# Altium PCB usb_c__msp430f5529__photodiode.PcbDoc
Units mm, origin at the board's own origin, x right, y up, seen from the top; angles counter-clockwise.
Board outline 62 x 34 mm, 2 copper layers (Top, Bottom), stack 0 mm thick; 27 components, 20 nets, 168 pads, 59 vias.
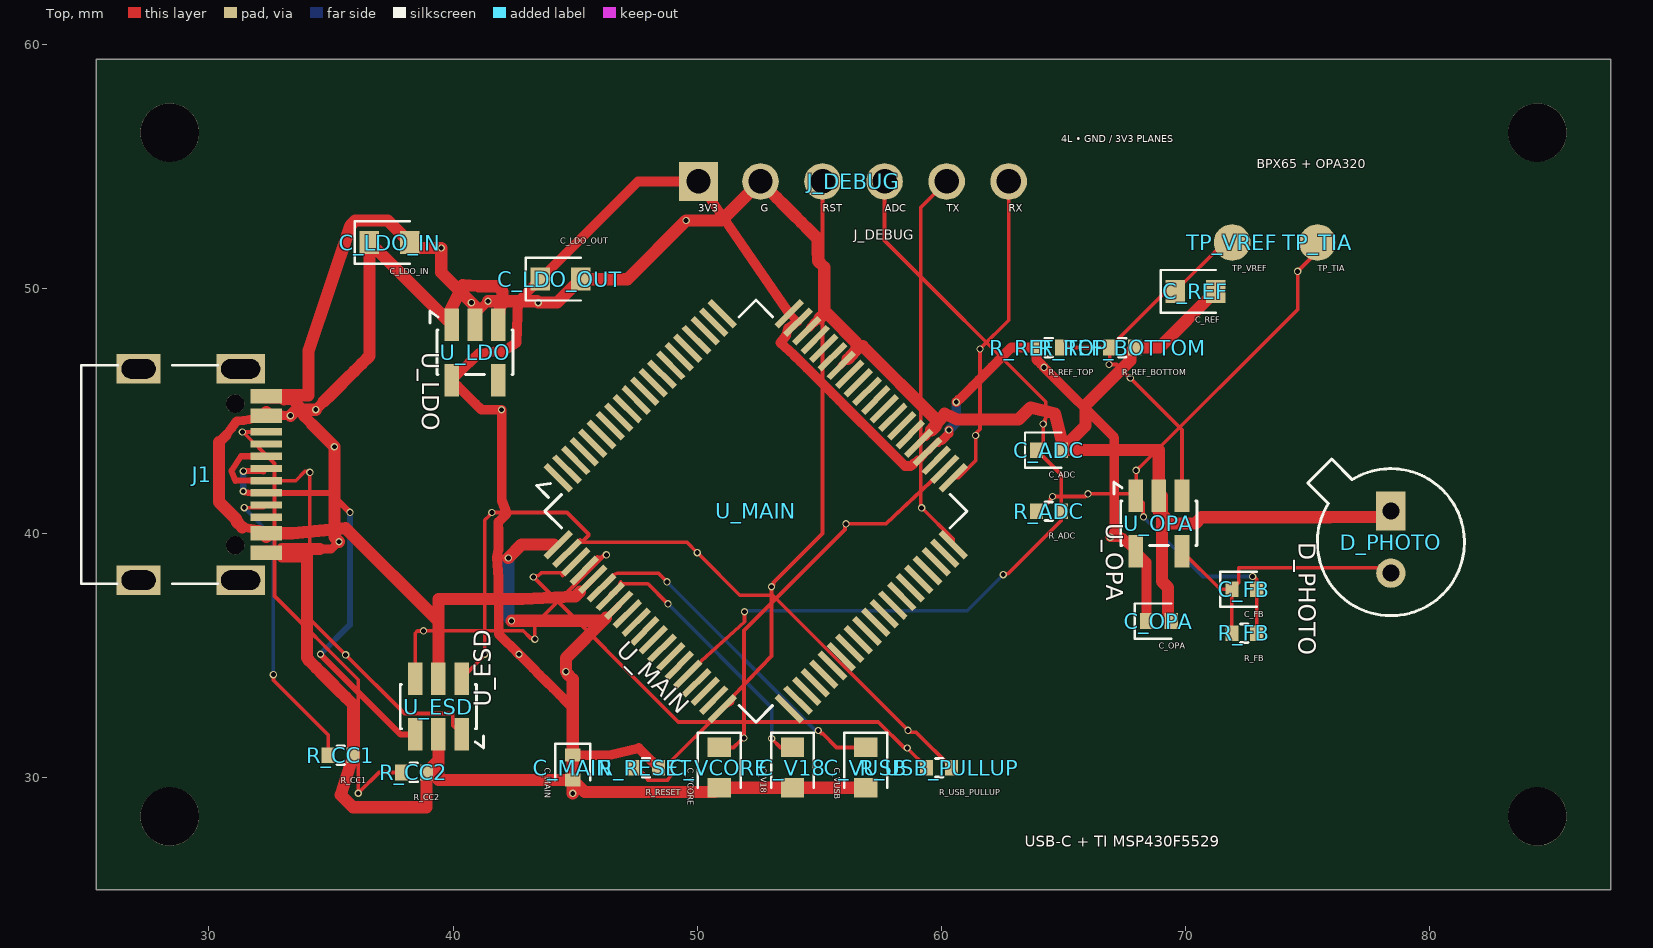
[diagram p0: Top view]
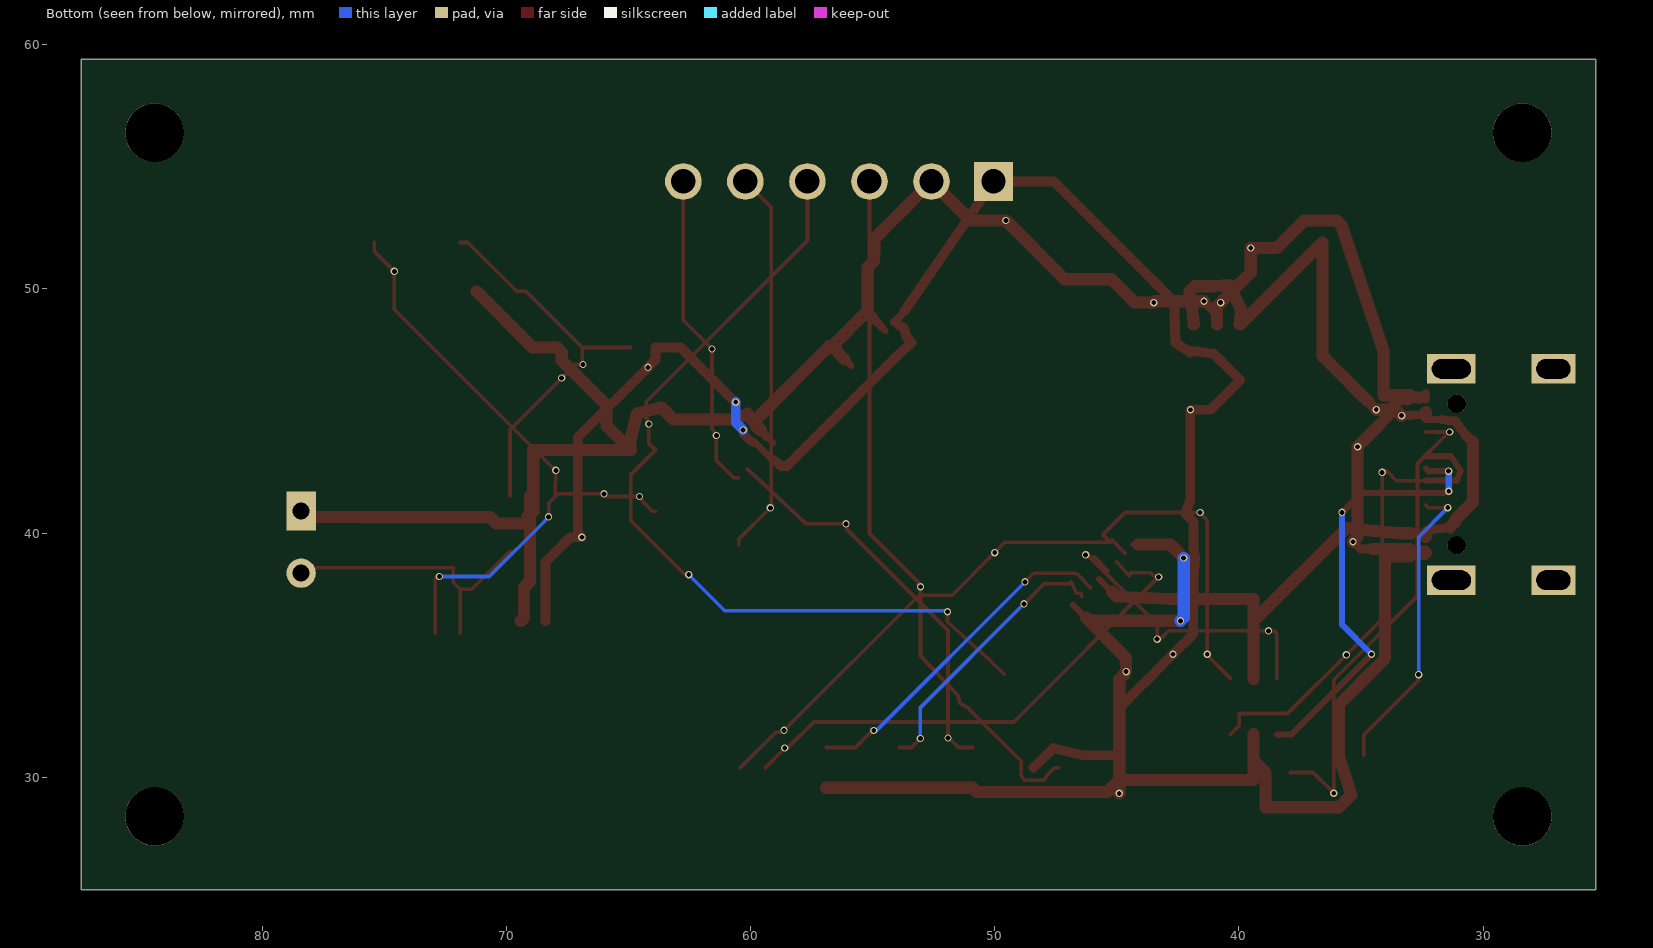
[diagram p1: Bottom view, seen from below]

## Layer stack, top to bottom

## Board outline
25.4,59.4 87.4,59.4 87.4,25.4 25.4,25.4

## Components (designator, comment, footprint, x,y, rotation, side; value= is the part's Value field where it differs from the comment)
C_ADC "" TSCIRCUIT-1.5600x0.6400mm 64.4,43.4 r0 top
C_FB "" TSCIRCUIT-1.5600x0.6400mm 72.4,37.7 r0 top
C_LDO_IN "" TSCIRCUIT-2.4500x0.9500mm 37.4,51.9 r0 top
C_LDO_OUT "" TSCIRCUIT-2.4500x0.9500mm 44.4,50.4 r0 top
C_MAIN "" TSCIRCUIT-0.6400x1.5600mm 44.9,30.4 r270 top
C_OPA "" TSCIRCUIT-1.5600x0.6400mm 68.9,36.4 r0 top
C_REF "" TSCIRCUIT-2.4500x0.9500mm 70.4,49.9 r0 top
C_V18 "" TSCIRCUIT-0.9500x2.4500mm 53.9,30.4 r270 top
C_VCORE "" TSCIRCUIT-0.9500x2.4500mm 50.9,30.4 r270 top
C_VUSB "" TSCIRCUIT-0.9500x2.4500mm 56.9,30.4 r270 top
D_PHOTO "" TSCIRCUIT-1.2000x3.9400mm 78.4,39.73 r270 top
J1 "" TSCIRCUIT-6.7732x9.8502mm 29.613,42.4 r90 top
J_DEBUG "" TSCIRCUIT-14.2000x1.5000mm 56.4,54.4 r0 top
R_ADC "" TSCIRCUIT-1.5600x0.6400mm 64.4,40.9 r0 top
R_CC1 "" TSCIRCUIT-1.5600x0.6400mm 35.4,30.9 r0 top
R_CC2 "" TSCIRCUIT-1.5600x0.6400mm 38.4,30.2 r0 top
R_FB "" TSCIRCUIT-1.5600x0.6400mm 72.4,35.9 r0 top
R_REF_BOTTOM "" TSCIRCUIT-1.5600x0.6400mm 67.4,47.6 r0 top
R_REF_TOP "" TSCIRCUIT-1.5600x0.6400mm 64.4,47.6 r0 top
R_RESET "" TSCIRCUIT-1.5600x0.6400mm 47.9,30.4 r0 top
R_USB_PULLUP "" TSCIRCUIT-1.5600x0.6400mm 59.9,30.4 r0 top
TP_TIA "" TSCIRCUIT-1.5000x1.5000mm 75.4,51.9 r0 top
TP_VREF "" TSCIRCUIT-1.5000x1.5000mm 71.9,51.9 r0 top
U_ESD "" TSCIRCUIT-2.5000x3.6000mm#1 39.4,32.9 r90 top
U_LDO "" TSCIRCUIT-2.5000x3.6000mm#2 40.9,47.4 r270 top
U_MAIN "" TSCIRCUIT-17.3948x17.3948mm 52.4,40.9 r315 top
U_OPA "" TSCIRCUIT-2.5000x3.6000mm#2 68.9,40.4 r270 top

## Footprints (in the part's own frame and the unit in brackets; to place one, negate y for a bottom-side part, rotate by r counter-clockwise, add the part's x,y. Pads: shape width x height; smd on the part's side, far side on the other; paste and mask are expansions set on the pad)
TSCIRCUIT-0.6400x1.5600mm [mm]
  rect 0.54x0.64 smd: 1(-0.51,0) 2(0.51,0)
  silkscreen extent -0.98,-0.72 0.51,0.72
TSCIRCUIT-0.9500x2.4500mm [mm]
  rect 0.8x0.95 smd: 1(-0.825,0) 2(0.825,0)
  silkscreen extent -1.43,-0.87 0.82,0.88
TSCIRCUIT-1.2000x3.9400mm [mm]
  rect 1.6x1.2 hole 0.7: 1(-1.17,0)
  round 1.2 hole 0.7: 2(1.37,0)
  silkscreen extent -3.3,-3.4 3.11,3.01
TSCIRCUIT-1.5000x1.5000mm [mm]
  round 1.5 smd: 1(0,0)
TSCIRCUIT-1.5600x0.6400mm [mm]
  rect 0.54x0.64 smd: 1(-0.51,0) 2(0.51,0)
  silkscreen extent -0.98,-0.72 0.51,0.72
TSCIRCUIT-2.4500x0.9500mm [mm]
  rect 0.8x0.95 smd: 1(-0.825,0) 2(0.825,0)
  silkscreen extent -1.42,-0.87 0.83,0.87
TSCIRCUIT-2.5000x3.6000mm#1 [mm]
  rect 1.325x0.6 smd: 1(-1.138,-0.95) 2(-1.138,0) 3(-1.138,0.95) 4(1.138,0.95) 5(1.138,0) 6(1.138,-0.95)
  silkscreen extent -1.69,-1.84 0.91,1.56
TSCIRCUIT-2.5000x3.6000mm#2 [mm]
  rect 1.325x0.6 smd: 1(-1.138,-0.95) 2(-1.138,0) 3(-1.138,0.95) 4(1.137,0.95) 5(1.137,-0.95)
  silkscreen extent -1.69,-1.84 0.91,1.56
TSCIRCUIT-6.7732x9.8502mm [mm]
  rect 1.2x2 hole 0.8 slot 1.6 at 90 deg: 1(-4.325,-1.693) 1(4.325,-1.693)
  rect 1.2x1.8 hole 0.8 slot 1.4 at 90 deg: 1(-4.325,2.487) 1(4.325,2.487)
  rect 0.3x1.3 smd: 1(-3.35,-2.737) 2(-3.05,-2.737) 3(-2.55,-2.737) 4(-2.25,-2.737) 5(-1.75,-2.737) 6(-1.25,-2.737) 7(-0.75,-2.737) 8(-0.25,-2.737) 9(0.25,-2.737) 10(0.75,-2.737) 11(1.25,-2.737) 12(1.75,-2.737) 13(2.55,-2.737) 14(2.25,-2.737) 15(3.35,-2.737) 16(3.05,-2.737)
  round 0.75 hole 0.75 unplated: NPTH-1(-2.9,-1.468) NPTH-2(2.9,-1.468)
  silkscreen extent -4.47,-0.75 4.47,4.83
TSCIRCUIT-14.2000x1.5000mm [mm]
  rect 1.6x1.6 hole 1: 1(-6.35,0)
  round 1.5 hole 1: 2(-3.81,0) 3(-1.27,0) 4(1.27,0) 5(3.81,0) 6(6.35,0)
TSCIRCUIT-17.3948x17.3948mm [mm]
  rect 1.475x0.25 smd: 1(-6.687,-4.75) 2(-6.687,-4.25) 3(-6.687,-3.75) 4(-6.687,-3.25) 5(-6.687,-2.75) 6(-6.687,-2.25) 7(-6.687,-1.75) 8(-6.687,-1.25) 9(-6.687,-0.75) 10(-6.687,-0.25) 11(-6.687,0.25) 12(-6.687,0.75) 13(-6.687,1.25) 14(-6.687,1.75) 15(-6.687,2.25) 16(-6.687,2.75) 17(-6.687,3.25) 18(-6.687,3.75) 19(-6.687,4.25) 20(-6.687,4.75) 41(6.688,4.75) 42(6.687,4.25) 43(6.687,3.75) 44(6.687,3.25) 45(6.688,2.75) 46(6.687,2.25) 47(6.687,1.75) 48(6.687,1.25) 49(6.687,0.75) 50(6.687,0.25) 51(6.687,-0.25) 52(6.687,-0.75) 53(6.687,-1.25) 54(6.687,-1.75) 55(6.687,-2.25) 56(6.687,-2.75) 57(6.687,-3.25) 58(6.687,-3.75) 59(6.687,-4.25) 60(6.687,-4.75)
  rect 0.25x1.475 smd: 21(-4.75,6.688) 22(-4.25,6.687) 23(-3.75,6.687) 24(-3.25,6.688) 25(-2.75,6.688) 26(-2.25,6.687) 27(-1.75,6.687) 28(-1.25,6.688) 29(-0.75,6.688) 30(-0.25,6.687) 31(0.25,6.687) 32(0.75,6.688) 33(1.25,6.688) 34(1.75,6.687) 35(2.25,6.687) 36(2.75,6.688) 37(3.25,6.688) 38(3.75,6.687) 39(4.25,6.687) 40(4.75,6.688) 61(4.75,-6.687) 62(4.25,-6.687) 63(3.75,-6.687) 64(3.25,-6.687) 65(2.75,-6.687) 66(2.25,-6.687) 67(1.75,-6.687) 68(1.25,-6.687) 69(0.75,-6.687) 70(0.25,-6.687) 71(-0.25,-6.687) 72(-0.75,-6.687) 73(-1.25,-6.687) 74(-1.75,-6.687) 75(-2.25,-6.687) 76(-2.75,-6.687) 77(-3.25,-6.687) 78(-3.75,-6.687) 79(-4.25,-6.687) 80(-4.75,-6.687)
  silkscreen extent -7.09,-6.11 6.11,6.11

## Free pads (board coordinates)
  round 2.4 hole 2.4 unplated: NPTH-3(28.4,28.4) NPTH-4(84.4,56.4) NPTH-5(84.4,28.4) NPTH-6(28.4,56.4)

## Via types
v1: diameter 0.3, hole 0.2, Top to Bottom, 59 vias

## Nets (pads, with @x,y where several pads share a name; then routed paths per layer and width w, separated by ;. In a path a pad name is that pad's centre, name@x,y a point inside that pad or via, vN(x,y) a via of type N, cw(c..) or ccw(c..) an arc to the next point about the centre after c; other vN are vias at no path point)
ADC_IN: C_ADC.1 J_DEBUG.4 R_ADC.2 U_MAIN.65 | length 35.3
  Top w0.15: U_MAIN.65 50.158,34.758 51.937,36.371 v1(51.937,36.782) ; J_DEBUG.4 57.67,51.979 64.266,45.382 64.266,44.686 64.239,44.658 64.239,44.541 v1(64.164,44.466) 64.164,43.674 C_ADC.1 64.91,42.38 R_ADC.2 64.91,40.526 62.719,38.336 62.562,38.336 v1(62.527,38.301)
  Bottom w0.15: v1(51.937,36.782) 51.981,36.826 52.139,36.826 61.052,36.826 v1(62.527,38.301)
GND: C_ADC.2 C_LDO_IN.2 C_LDO_OUT.2 C_MAIN.2 C_OPA.2 C_REF.2 C_V18.2 C_VCORE.2 C_VUSB.2 D_PHOTO.1 J1.1@32.349,39.05 J1.2 J1.15 J1.16 J_DEBUG.2 R_CC1.2 R_CC2.2 R_REF_BOTTOM.2 U_ESD.2 U_LDO.2 U_MAIN.23 U_MAIN.27 U_MAIN.36 U_MAIN.73 U_MAIN.80 U_OPA.2 | length 158.4
  Top w0.25: 44.136,39.53 U_MAIN.80 ; U_MAIN.23@54.623,48.426 U_MAIN.23 54.837,48.621 U_MAIN.23@55.008,48.792 ; U_MAIN.27 U_MAIN.27@56.164,47.129 ; U_MAIN.36@59.342,43.952 U_MAIN.36 U_MAIN.36@59.595,44.206 ; U_MAIN.73@46.266,36.534 U_MAIN.73 U_MAIN.73@46.266,36.534
  Top w0.278: U_MAIN.27 56.164,47.129 56.525,47.525
  Top w0.288: J1.15@32.349,45.6 J1.16 32.446,45.468 J1.16@32.537,45.45
  Top w0.3: J1.16@32.349,45.6 J1.15 32.4,45.65 32.999,45.65 ; J1.2@32.446,39.332 J1.2 32.349,39.2 32.349,39.05 32.999,39.05 ; J1.2@32.537,39.35 32.63,39.35 32.724,39.35 32.818,39.35 32.911,39.35 J1.2@32.999,39.35 ; J1.16@32.63,45.45 32.724,45.45 33.078,45.456
  Top w0.301: J1.2@32.446,39.332 J1.2@32.537,39.35 ; J1.16@32.537,45.45 J1.16@32.63,45.45
  Top w0.328: U_MAIN.23@54.623,48.426 54.624,48.426 U_MAIN.23@54.804,48.626
  Top w0.347: U_MAIN.36@59.342,43.952 59.352,43.952 U_MAIN.36@59.525,44.15
  Top w0.35: 34.54,39.35 35.021,39.35 v1(35.332,39.646)
  Top w0.363: U_MAIN.23@54.804,48.626 U_MAIN.23@55.004,48.797
  Top w0.375: U_LDO.2@40.9,48.953 41.169,49.222 v1(41.434,49.493)
  Top w0.397: U_MAIN.36@59.525,44.15 U_MAIN.36@59.581,44.219
  Top w0.437: 33.65,45.244 33.869,45.025 33.869,44.806 34.235,44.476
  Top w0.45: 33.078,45.456 33.431,45.462 33.65,45.244 ; 34.235,44.444 34.235,44.476
  Top w0.5: 32.999,39.05 34.025,39.05 34.025,34.9 34.093,34.792 34.396,34.489 34.699,34.186 35.002,33.883 35.304,33.58 35.607,33.278 35.91,32.975 35.91,32.56 35.91,32.145 35.91,31.73 35.91,31.315 R_CC1.2 35.4,29.275 35.9,28.775 38.91,28.775 R_CC2.2 39.4,30.69 U_ESD.2 39.4,29.89 C_MAIN.2 ; 32.999,39.35 33.005,39.35 33.099,39.35 33.58,39.35 34.06,39.35 34.54,39.35 ; 32.999,45.65 34.084,45.65 34.084,47.485 35.8,52.6 36,52.8 37.325,52.8 C_LDO_IN.2 38.448,51.677 v1(39.516,51.677) 39.516,50.672 v1(40.749,49.439) 40.9,49.288 U_LDO.2 U_LDO.2@40.9,48.953 ; 34.235,44.444 v1(35.141,43.538) 35.141,39.837 v1(35.332,39.646) ; v1(41.434,49.493) 43.433,49.493 v1(43.487,49.439) 43.876,49.439 44.264,49.439 44.584,49.759 44.905,50.08 C_LDO_OUT.2 47.144,50.4 v1(49.545,52.801) 50.991,52.801 J_DEBUG.2 52.924,54.066 53.258,53.732 53.592,53.398 53.926,53.064 54.26,52.73 54.593,52.397 54.927,52.063 54.935,51.6 54.943,51.138 55.197,50.884 55.197,48.963 ; v1(42.263,38.985) 42.808,39.53 44.136,39.53 ; v1(42.395,36.409) 46.141,36.409 46.266,36.534 44.62,34.888 v1(44.62,34.329) 44.672,34.277 44.672,34.248 44.9,34.019 44.9,33.552 44.9,33.084 44.9,32.616 44.9,32.149 44.9,31.681 44.9,31.214 44.9,30.746 44.9,30.278 44.9,29.811 v1(44.9,29.343) 44.9,29.39 C_MAIN.2 ; 55.004,48.797 55.197,48.963 ; 55.008,48.793 55.178,48.963 55.197,48.963 ; U_MAIN.27@56.164,47.129 56.65,47.65 56.775,47.65 59.775,44.65 59.775,44.386 U_MAIN.36@59.595,44.206 ; 56.525,47.525 56.525,47.789 55.451,48.864 55.352,48.963 55.197,48.963 ; C_VUSB.2 C_V18.2 C_VCORE.2 50.725,29.4 49.15,29.4 45.39,29.4 C_MAIN.2 ; 59.581,44.219 60.126,44.887 60.65,44.65 63.15,44.65 63.65,45.15 64.65,44.9 64.91,43.825 C_ADC.2 ; C_OPA.2 69.4,36.4 69.275,36.525 69.275,37.775 69.025,38.025 69.025,41.525 68.913,41.525 U_OPA.2 ; C_REF.2 68.925,47.6 R_REF_BOTTOM.2 67.91,47.577 67.733,47.4 67.733,47.067 65.9,45.233 65.9,44.4 64.9,43.4 C_ADC.2 ; D_PHOTO.1 78.159,40.659 77.661,40.659 77.163,40.659 76.665,40.659 76.167,40.659 75.909,40.659 75.9,40.65 70.65,40.65 70.4,40.4 69.15,40.4 69.15,40.65 68.9,40.9 U_OPA.2 ; C_ADC.2 68.9,43.4 U_OPA.2
  Bottom w0.5: v1(42.263,38.985) 42.263,36.541 v1(42.395,36.409)
MAIN_RESET: J_DEBUG.3 R_RESET.1 U_MAIN.61 | length 28.8
  Top w0.15: R_RESET.1 47.548,30.4 47.79,30.158 47.976,29.893 48.243,29.888 48.503,29.887 48.782,29.892 48.923,30.081 48.916,30.107 48.916,30.657 50.825,32.564 51.03,32.771 U_MAIN.61 51.431,33.034 51.523,33.382 53.038,34.97 v1(53.038,37.804) 53.124,37.89 53.124,37.981 55.13,39.986 J_DEBUG.3
MSP_USB_PUR: R_USB_PULLUP.1 U_MAIN.78 | length 21.4
  Top w0.15: U_MAIN.78 44.495,38.255 44.42,38.372 43.613,38.372 43.494,38.254 43.344,38.254 v1(43.291,38.201) 49.223,32.269 57.178,32.269 57.415,32.269 58.484,31.2 v1(58.6,31.2) 58.6,31.19 R_USB_PULLUP.1
MSP_V18: C_V18.1 U_MAIN.74 | length 11.4
  Top w0.15: U_MAIN.74 46.461,37.526 46.674,37.559 46.873,38.002 46.895,37.926 47.979,37.926 v1(48.802,37.103) ; v1(53.044,31.588) 53.049,31.583 53.407,31.225 C_V18.1
  Bottom w0.15: v1(48.802,37.103) 48.819,37.086 53.044,32.861 v1(53.044,31.588)
MSP_VCORE: C_VCORE.1 U_MAIN.39 | length 16.6
  Top w0.15: C_VCORE.1 51.484,31.225 51.778,31.519 51.823,31.519 v1(51.917,31.613) 51.917,36.014 56.052,40.149 56.052,40.344 v1(56.088,40.38) 57.714,40.38 59.574,42.11 U_MAIN.39
MSP_VUSB: C_VUSB.1 U_MAIN.75 | length 14
  Top w0.15: U_MAIN.75 46.615,38.321 46.736,38.354 48.416,38.354 v1(48.763,38.007) ; v1(54.954,31.921) 55.082,31.793 55.135,31.793 55.704,31.225 C_VUSB.1
  Bottom w0.15: v1(48.763,38.007) 48.817,37.953 48.817,37.951 54.846,31.921 v1(54.954,31.921)
PD_SUM: C_FB.1 D_PHOTO.2 R_FB.1 U_OPA.4 | length 11.8
  Top w0.15: U_OPA.4 71.412,37.7 C_FB.1 ; R_FB.1 C_FB.1 ; D_PHOTO.2 78.177,38.583 72.171,38.583 72.171,37.981 C_FB.1
TIA_OUT: C_FB.2 R_ADC.1 R_FB.2 TP_TIA.1 U_OPA.1 | length 26.8
  Top w0.15: R_ADC.1 64.016,40.9 64.457,41.341 64.457,41.412 v1(64.544,41.499) 65.893,41.499 65.998,41.604 v1(66.001,41.607) 67.88,41.607 U_OPA.1 ; v1(68.268,40.666) 68.268,41.219 U_OPA.1 ; v1(72.742,38.226) 72.798,38.17 72.839,38.17 72.91,38.099 C_FB.2 R_FB.2 ; TP_TIA.1 75.4,51.536 74.597,50.733 v1(74.583,50.719) 74.583,49.157 68.12,42.694 68.094,42.694 v1(67.97,42.57) 68,41.587 U_OPA.1
  Bottom w0.15: v1(68.268,40.666) 68.429,40.505 68.429,40.49 70.693,38.226 v1(72.742,38.226)
UART_MAIN_RX: J_DEBUG.6 U_MAIN.40 | length 13.2
  Top w0.15: U_MAIN.40 60.7,42.27 60.726,42.296 61.4,42.97 v1(61.4,44) 61.429,44.029 61.429,44.102 61.58,44.253 v1(61.58,47.538) 61.641,47.599 61.641,47.61 62.75,48.719 J_DEBUG.6
UART_MAIN_TX: J_DEBUG.5 U_MAIN.41 | length 15.9
  Top w0.15: J_DEBUG.5 59.158,53.348 59.158,41.227 59.158,41.066 v1(59.188,41.036) 60.488,39.737 U_MAIN.41
USB_CC1: J1.6 R_CC1.1 | length 12.5
  Top w0.15: v1(31.449,41.044) 32.243,41.044 J1.6 ; v1(32.641,34.208) 32.65,34.199 32.65,33.972 34.89,31.732 R_CC1.1
  Bottom w0.15: v1(31.449,41.044) 31.5,40.993 31.5,40.984 32.641,39.843 v1(32.641,34.208)
USB_CC2: J1.12 R_CC2.1 | length 19.9
  Top w0.15: J1.12 32.342,44.143 v1(31.374,44.143) 31.381,44.15 31.389,44.15 32.69,42.848 32.69,37.428 36.12,33.998 v1(36.12,29.35) 36.205,29.435 36.205,29.439 36.966,30.2 R_CC2.1
USB_DM_MCU: U_ESD.4 U_MAIN.77 | length 12.8
  Top w0.15: U_ESD.4 38.45,35.897 38.549,35.996 38.789,35.996 v1(38.792,35.999) 42.876,35.999 43.17,35.706 43.304,35.706 v1(43.349,35.661) 43.349,36.255 46.181,39.087 46.255,39.087 v1(46.279,39.111) 46.186,39.111 46.077,39.002 45.908,39.029 U_MAIN.77
USB_DM_PORT: J1.7 J1.9 U_ESD.3 | length 18.1
  Top w0.25: v1(31.41,41.716) 31.466,41.66 31.603,41.66 31.613,41.65 J1.7 34.977,41.65 35.77,40.857 v1(35.778,40.849) ; v1(31.414,42.538) 32.232,42.533 J1.9 ; v1(34.571,35.039) 37.848,31.762 U_ESD.3
  Bottom w0.25: v1(31.41,41.716) 31.41,42.464 31.41,42.529 v1(31.414,42.538) ; v1(34.571,35.039) 34.614,35.082 35.778,36.246 v1(35.778,40.849)
USB_DP_MCU: R_USB_PULLUP.2 U_ESD.6 U_MAIN.79 | length 32.9
  Top w0.15: U_ESD.6 40.35,34.049 41.319,35.018 v1(41.298,35.039) 41.298,40.534 41.478,40.714 41.478,40.737 v1(41.588,40.847) 44.662,40.847 45.545,39.963 45.545,39.906 45.265,39.626 ; R_USB_PULLUP.2 58.959,31.851 58.761,31.851 58.704,31.851 v1(58.631,31.924) 53.093,37.462 51.926,37.462 51.742,37.462 50.108,39.096 v1(50.002,39.202) 49.578,39.626 45.265,39.626 ; 45.201,39.736 45.265,39.626 ; 45.201,39.736 U_MAIN.79 45.201,39.736 ; 45.201,39.736 45.265,39.626
USB_DP_PORT: J1.8 J1.10 U_ESD.1 | length 19.9
  Top w0.15: J1.8 33.557,42.15 33.94,42.533 34.092,42.533 v1(34.138,42.487) 34.138,36.481 35.527,35.092 v1(35.604,35.015) 38.009,32.615 39.993,32.615 39.993,32.119 U_ESD.1
  Top w0.25: J1.8 31.091,42.147 30.925,42.556 31.324,43.15 J1.10
VBUS5: C_LDO_IN.1 J1.3 J1.4 J1.13 J1.14 U_ESD.5 U_LDO.1 U_LDO.3 U_MAIN.76 | length 48.3
  Top w0.25: U_MAIN.76@45.201,37.598 U_MAIN.76
  Top w0.275: J1.3 J1.3@32.489,39.993
  Top w0.3: 31.678,44.65 32.014,44.65 J1.14 32.349,44.8 ; J1.4@32.064,40.15 J1.4 J1.3@32.349,40
  Top w0.303: J1.3@32.489,39.993 J1.3@32.96,39.994
  Top w0.356: J1.13 32.451,44.848 32.896,44.829 32.999,44.824
  Top w0.375: 30.726,44.033 30.938,44.31 31.15,44.588 31.414,44.619 31.678,44.65 ; 31.369,40.244 31.716,40.197 J1.4@32.064,40.15 ; v1(34.38,45.055) v1@34.399,45.074
  Top w0.4: 32.999,44.824 v1(33.341,44.809)
  Top w0.425: 30.418,43.725 30.726,44.033 ; v1@34.399,45.074 34.71,45.385
  Top w0.5: 30.418,43.725 30.418,41.274 31.137,40.554 31.137,40.475 31.369,40.244 ; J1.3 J1.4@32.349,40 ; J1.13@32.349,44.8 J1.13 ; J1.3@32.96,39.994 33.432,39.995 35.6,40.2 39.4,36.4 U_ESD.5 39.4,37.301 42.838,37.301 45,37.4 U_MAIN.76@45.201,37.598 ; v1(33.341,44.809) 33.587,45.055 v1(34.38,45.055) ; 34.71,45.385 35.02,45.695 35.331,46.006 35.642,46.317 35.953,46.628 36.264,46.939 36.575,47.25 36.575,47.715 36.575,48.18 36.575,48.645 36.575,49.11 36.575,49.575 36.575,50.04 36.575,50.505 36.575,50.97 36.575,51.435 C_LDO_IN.1 36.588,51.9 U_LDO.1 39.973,48.56 39.9,49.15 40.4,50.15 41.052,50.113 41.812,50.113 42.025,49.9 42.025,49.4 41.925,49.258 41.888,48.898 U_LDO.3
VCC_3V3: C_LDO_OUT.1 C_MAIN.1 C_OPA.1 J_DEBUG.1 R_REF_TOP.1 R_RESET.2 U_LDO.5 U_MAIN.21 U_MAIN.22 U_MAIN.37 U_OPA.5 | length 73.5
  Top w0.25: U_MAIN.21@53.698,49.092 U_MAIN.21 53.858,48.899 ; U_MAIN.37@59.184,43.056 U_MAIN.37 ; U_MAIN.37@59.861,43.751 59.875,43.652 U_MAIN.37@60.012,43.789
  Top w0.274: U_MAIN.37 59.644,43.541 U_MAIN.37@59.861,43.751
  Top w0.288: U_MAIN.37@59.038,43.003 U_MAIN.37@59.184,43.056
  Top w0.312: U_MAIN.22@53.925,48.524 U_MAIN.22 ; 53.947,48.811 U_MAIN.22
  Top w0.325: 53.858,48.899 53.947,48.811
  Top w0.346: U_MAIN.37@58.864,42.85 U_MAIN.37@59.038,43.003
  Top w0.363: U_MAIN.37@60.012,43.789 60.09,43.866 60.304,44.081 v1(60.304,44.222)
  Top w0.4: R_RESET.2 48.155,30.655 47.6,31.2 46.4,30.91 46.025,30.91 45.65,30.91 45.275,30.91 C_MAIN.1 44.9,31.297 44.9,31.684 44.9,32.071 44.9,32.458 44.9,32.845 44.629,33.116 44.358,33.387 44.087,33.658 43.817,33.928 43.546,34.199 43.275,34.47 43.004,34.741 42.733,35.012 v1(42.702,35.043) 42.425,35.314 42.149,35.586 41.872,35.857 41.871,36.241 41.87,36.624 41.868,37.007 41.867,37.39 41.865,37.773 41.864,38.156 41.8,39 41.86,39.305 41.858,39.688 41.857,40.071 41.855,40.455 42.2,40.8 41.996,41.343 41.996,41.732 41.996,42.122 41.996,42.512 41.996,42.902 41.996,43.291 41.996,43.681 41.996,44.071 41.996,44.461 41.996,44.851 41.996,45.045 v1(41.988,45.053) 41.712,45.053 41.435,45.053 41.159,45.053 40.917,45.295 40.675,45.537 40.434,45.779 40.192,46.021 U_LDO.5 40.222,46.535 40.494,46.807 40.767,47.079 41.039,47.351 41.376,47.392 41.713,47.434 42.05,47.475 42,47.4 42.6,47.8 42.661,49.486 42.89,49.715 43.118,49.943 43.347,50.172 C_LDO_OUT.1 47.575,54.4 J_DEBUG.1 50.565,53.65 53.698,49.092 ; U_MAIN.22@53.925,48.524 53.727,48.414 53.632,48.088 53.4,47.8 53.952,47.298 54.22,47.03 54.488,46.763 54.756,46.495 55.024,46.227 55.292,45.959 55.56,45.691 55.828,45.424 56.096,45.156 56.365,44.888 56.633,44.62 56.901,44.352 57.169,44.085 57.437,43.817 57.705,43.549 57.973,43.281 58.241,43.013 58.51,42.746 58.745,42.746 58.864,42.85 ; v1(60.606,45.365) 60.719,45.478 60.734,45.478 60.999,45.743 61.265,46.008 61.53,46.274 61.795,46.539 62.06,46.804 62.326,47.069 62.591,47.335 62.856,47.6 63.201,47.6 63.545,47.6 R_REF_TOP.1 63.89,47.099 64.066,46.923 64.066,46.92 v1(64.196,46.79) 67.078,43.908 67.078,39.939 67.015,39.939 v1(66.907,39.831) 67.381,39.831 U_OPA.5 68.39,38.822 C_OPA.1
  Bottom w0.4: v1(60.304,44.222) 60.318,44.236 60.462,44.38 60.606,44.524 60.606,44.804 60.606,45.085 v1(60.606,45.365)
VREF_0V5: C_REF.1 R_REF_BOTTOM.1 R_REF_TOP.2 TP_VREF.1 U_OPA.3 | length 16.3
  Top w0.15: R_REF_TOP.2 R_REF_BOTTOM.1 ; U_OPA.3 69.85,44.236 v1(67.733,46.353) 67.67,46.416 67.654,46.416 67.163,46.907 v1(66.859,46.907) 66.89,46.938 66.89,47.1 R_REF_BOTTOM.1 ; TP_VREF.1 71.575,51.9 C_REF.1 69.19,49.9 R_REF_BOTTOM.1
pads on no net: J1.1@27.126,38.075 J1.1@27.126,46.725 J1.1@31.306,38.075 J1.1@31.306,46.725 J1.5 J1.11 J1.NPTH-1 J1.NPTH-2 U_LDO.4 U_MAIN.1 U_MAIN.2 U_MAIN.3 U_MAIN.4 U_MAIN.5 U_MAIN.6 U_MAIN.7 U_MAIN.8 U_MAIN.9 U_MAIN.10 U_MAIN.11 U_MAIN.12 U_MAIN.13 U_MAIN.14 U_MAIN.15 U_MAIN.16 U_MAIN.17 U_MAIN.18 U_MAIN.19 U_MAIN.20 U_MAIN.24 U_MAIN.25 U_MAIN.26 U_MAIN.28 U_MAIN.29 U_MAIN.30 U_MAIN.31 U_MAIN.32 U_MAIN.33 U_MAIN.34 U_MAIN.35 U_MAIN.38 U_MAIN.42 U_MAIN.43 U_MAIN.44 U_MAIN.45 U_MAIN.46 U_MAIN.47 U_MAIN.48 U_MAIN.49 U_MAIN.50 U_MAIN.51 U_MAIN.52 U_MAIN.53 U_MAIN.54 U_MAIN.55 U_MAIN.56 U_MAIN.57 U_MAIN.58 U_MAIN.59 U_MAIN.60 U_MAIN.62 U_MAIN.63 U_MAIN.64 U_MAIN.66 U_MAIN.67 U_MAIN.68 U_MAIN.69 U_MAIN.70 U_MAIN.71 U_MAIN.72

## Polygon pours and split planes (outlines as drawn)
GND on Mid1 (solid): 87.1,59.1 25.7,59.1 25.7,25.7 87.1,25.7
VCC_3V3 on Mid2 (solid): 87.1,59.1 25.7,59.1 25.7,25.7 87.1,25.7

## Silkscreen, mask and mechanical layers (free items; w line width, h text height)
Top Overlay:
  text "4L • GND / 3V3 PLANES" at 64.9,55.9 h0.48
  text "BPX65 + OPA320" at 72.9,54.8 h0.65
  text "USB-C + TI MSP430F5529" at 63.4,27 h0.78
